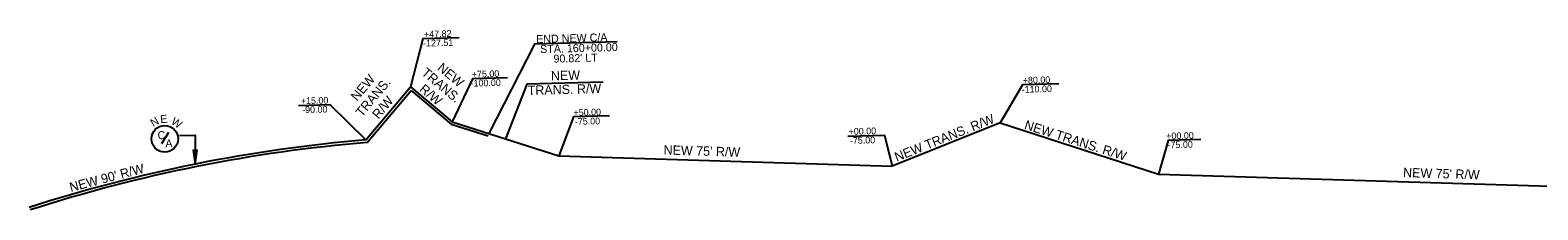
# Model space of a CAD drawing. Extents: x 2003184 to 2010449, y 855784 to 861212.
# Drawn here: x 2005713 to 2006844, y 858199 to 858334 of the extents above; entities that cross this region are included whole.
import ezdxf

# ---------------------------------------------------------------- set-up
doc = ezdxf.new("R2010")
doc.units = 0
for name, color, linetype in [('RD_PD_Control_Access', 7, 'Continuous'), ('RD_PD_RW', 7, 'Continuous'), ('RD_PD_RW_TX', 7, 'Continuous')]:
    doc.layers.add(name, color=color, linetype=linetype)

msp = doc.modelspace()

# ---------------------------------------------------------------- linework, layer by layer
at = {"layer": 'RD_PD_Control_Access'}
for p, q in [((2005966, 858249.5), (2005998.9, 858288.5)), ((2005998.9, 858288.5), (2006028.9, 858263.3)), ((2005817, 858257), (2005811.7, 858248.5)), ((2006028.9, 858263.3), (2006056.7, 858254.4))]:
    msp.add_line(p, q, dxfattribs=at)
for points in [[(2006153.6, 858325), (2006091.4, 858323.3), (2006057.3, 858256.3)], [(2005825.2, 858254.7), (2005837.1, 858255), (2005837.1, 858233.3)]]:
    msp.add_lwpolyline(points, dxfattribs=at)
msp.add_lwpolyline([(2005837.1, 858233.3), (2005838.6, 858243.6), (2005837.1, 858242), (2005835.6, 858243.6)], close=True, dxfattribs=at)
msp.add_circle((2005814.2, 858252.2), 10, dxfattribs=at)
msp.add_arc((2006059.8, 857126.4), 1127, 94.7746, 107.9087, dxfattribs=at)
at = {"layer": 'RD_PD_RW'}
for p, q in [((2005965, 858251.5), (2005998.6, 858291.3)), ((2005998.6, 858291.3), (2006029.8, 858265)), ((2006029.8, 858265), (2006109.8, 858239.4)), ((2006440.7, 858264.3), (2006359.6, 858231.8)), ((2006440.7, 858264.3), (2006559.5, 858225.6)), ((2006109.8, 858239.4), (2006359.6, 858231.8)), ((2006559.5, 858225.6), (2006959.4, 858213.4))]:
    msp.add_line(p, q, dxfattribs=at)
msp.add_arc((2006059.8, 857126.4), 1129, 94.8168, 107.9087, dxfattribs=at)
at = {"layer": 'RD_PD_RW_TX'}
for points in [[(2006035, 858328.1), (2006007.7, 858327.3), (2005998.6, 858291.3)], [(2006071.3, 858298), (2006045.1, 858297.3), (2006029.8, 858265)], [(2006142.9, 858294.9), (2006085.7, 858293.3), (2006069.8, 858252.2)], [(2006484.6, 858293.5), (2006457.5, 858292.7), (2006440.7, 858264.3)], [(2005914.6, 858277.3), (2005937.9, 858278), (2005965, 858251.5)], [(2006147.7, 858269.4), (2006120.7, 858268.7), (2006109.8, 858239.4)], [(2006326.5, 858254.2), (2006354, 858254.9), (2006359.6, 858231.8)], [(2006591.1, 858251.6), (2006566.8, 858251), (2006559.5, 858225.6)]]:
    msp.add_lwpolyline(points, dxfattribs=at)

# ---------------------------------------------------------------- texts
at = {"layer": 'RD_PD_Control_Access'}
for s, rotation, p in [('END NEW C/A', 1.6093, (2006092.8, 858324.1)), ('STA. 160+00.00', 1.6093, (2006095.8, 858316.6)), ("90.82' LT", 1.6093, (2006105.8, 858309.4)), ('N', 30.9213, (2005805.6, 858261)), ('E', 5.803, (2005811.1, 858263.9)), ('W', 328.1255, (2005818.4, 858263.7)), ('C', 1.6093, (2005808.9, 858251.9)), ('A', 1.6093, (2005814.7, 858245.7))]:
    msp.add_text(s, height=6, rotation=rotation, dxfattribs=at).set_placement(p)
at = {"layer": 'RD_PD_RW_TX'}
for s, height, rotation, p in [('-127.51', 5, 1.6093, (2006008, 858321.5)), ('+47.82', 5, 1.6093, (2006008.7, 858328.3)), ('TRANS. ', 7, 319.88, (2006006.2, 858300.9)), ('NEW', 7, 319.88, (2006018.1, 858304.6)), ('+75.00', 5, 1.6093, (2006044.5, 858298.2)), ('NEW', 7, 1.6093, (2006103.9, 858296.1)), ('NEW', 7, 49.88, (2005958.4, 858280.1)), ('TRANS. ', 7, 49.88, (2005962.1, 858268.2)), ('R/W', 7, 319.88, (2006004.6, 858288.6)), ('-100.00', 5, 1.6093, (2006043.6, 858291.4)), ('TRANS. R/W', 7, 1.6093, (2006086.5, 858285.1)), ('-110.00', 5, 1.6093, (2006456.9, 858286.8)), ('+80.00', 5, 1.6093, (2006457.7, 858293.6)), ('+15.00', 5, 1.6093, (2005916.3, 858278.2)), ('R/W', 7, 49.88, (2005974.5, 858266.6)), ('-90.00', 5, 1.6093, (2005917.3, 858271.5)), ('+50.00', 5, 1.6093, (2006120.8, 858269.4)), ('-75.00', 5, 1.6093, (2006121.8, 858262.7)), ('NEW TRANS. R/W', 7, 21.8192, (2006363.2, 858235)), ('+00.00', 5, 1.6093, (2006327.1, 858255.2)), ('NEW TRANS. R/W', 7, 342.3555, (2006458.3, 858259.8)), ('+00.00', 5, 1.6093, (2006565.3, 858251.8)), ("NEW 75' R/W", 7, 358.2422, (2006188.2, 858240.5)), ('-75.00', 5, 1.6093, (2006328.1, 858248.4)), ('-75.00', 5, 1.6093, (2006566.3, 858245.1)), ("NEW 90' R/W", 7, 14.7099, (2005743.8, 858212.3)), ("NEW 75' R/W", 7, 358.2422, (2006742.8, 858223.5))]:
    msp.add_text(s, height=height, rotation=rotation, dxfattribs=at).set_placement(p)

doc.saveas('drawing.dxf')
